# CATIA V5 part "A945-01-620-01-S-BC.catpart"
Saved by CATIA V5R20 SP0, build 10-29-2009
Part number: A945-01-620-01-S-BC
Source: Unknown
Property "ARTICLENO": "A945-01-620-01-S-BC"
Property "B": "65.000"
Property "BOMINFO": "A945-01-620-01-S-BC"
Property "CODE": "A945-01-620-01-S-BC"
Property "D1": "20.000"
Property "D2": "13.500"
Property "D5": "16.000"
Property "D6": "12.000"
Property "H": "47.000"
Property "H1": "34.000"
Property "H2": "35.000"
Property "H3": "18.000"
Property "L1": "200.000"
Property "L2": "25.000"
Property "L3": "0.000"
Property "L4": "150.000"
Property "L5": "55.000"
Property "L6": "95.000"
Property "LINA": "A945-01-620-01-S-BC"
Property "N": "2.000"
Property "NB": "A945-01-620-01-S-BC"
Property "NBSYN": " $CODE."
Property "NN": "A945-01"
Property "NT": "v driver sets replaceable inserts pisitive return"
Property "SUPPLIER": "CF"
Property "Z": "65.000"
Bounding box of the stored display mesh (mm): x -5049.207 to -4951.207, y -575.36 to -510.36, z 0 to 200
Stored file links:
  C:\Users\Utente\Desktop\3D files A945-01\A945-01-620-01-S-BC.catpart
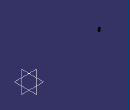
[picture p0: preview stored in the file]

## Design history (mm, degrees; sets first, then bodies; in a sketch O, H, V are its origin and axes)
Body1 "Geometry.1" (main body)
  Solid1 "A945-01-620-01-S-BC.catpart": solid without history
